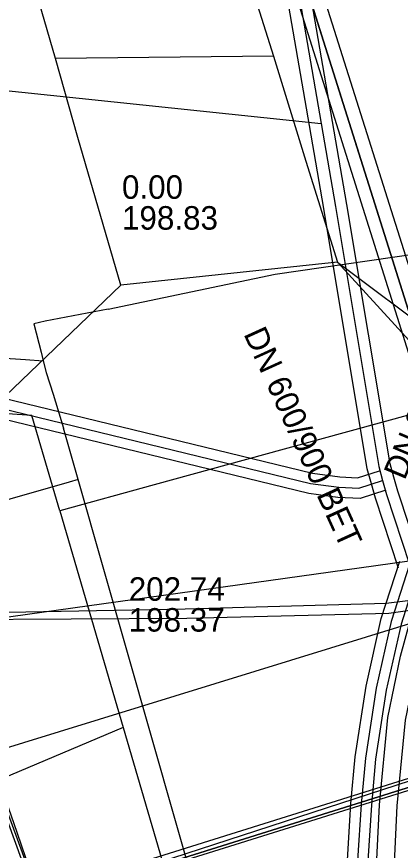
# Model space of a CAD drawing. Extents: x -600309 to -598967, y -1161267 to -1160292.
# Drawn here: x -599245.49 to -599232.41, y -1161251.1 to -1161222.72 of the extents above; entities that cross this region are included whole.
import ezdxf

# ---------------------------------------------------------------- set-up
doc = ezdxf.new("R2010")
doc.units = 0
for name, color, linetype in [('Vrstva 10', 7, 'Continuous'), ('Vrstva 12', 7, 'Continuous'), ('Vrstva 13', 7, 'Continuous'), ('Vrstva 16', 7, 'Continuous'), ('Vrstva 42', 7, 'Continuous'), ('Vrstva 44', 7, 'Continuous'), ('Vrstva 54', 7, 'Continuous'), ('Vrstva 55', 7, 'Continuous'), ('Vrstva 58', 7, 'Continuous'), ('Vrstva 9', 7, 'Continuous')]:
    doc.layers.add(name, color=color, linetype=linetype)

msp = doc.modelspace()

# ---------------------------------------------------------------- linework, layer by layer
at = {"layer": 'Vrstva 10'}
for p, q in [((-599237.17, -1161218.22), (-599221.784, -1161267.031)), ((-599236.22, -1161218.29), (-599220.801, -1161267.031)), ((-599234.235, -1161229.117), (-599234.724, -1161226.291)), ((-599235.024, -1161229.254), (-599235.513, -1161226.427))]:
    msp.add_line(p, q, dxfattribs=at)
for points in [[(-599234.724, -1161226.291), (-599239.864, -1161196.586), (-599240.106, -1161195.933), (-599240.701, -1161195.25)], [(-599235.513, -1161226.427), (-599240.639, -1161196.796), (-599240.805, -1161196.348), (-599241.304, -1161195.776)], [(-599303.586, -1161224.015), (-599302.565, -1161223.81), (-599300.956, -1161223.673), (-599298.819, -1161223.863), (-599269.258, -1161230.047), (-599235.407, -1161238.263), (-599234.478, -1161238.388), (-599233.878, -1161238.413), (-599233.122, -1161238.174)], [(-599232.911, -1161238.841), (-599233.784, -1161239.118), (-599234.54, -1161239.086), (-599235.536, -1161238.952), (-599269.412, -1161230.73), (-599298.922, -1161224.556), (-599300.958, -1161224.376), (-599302.466, -1161224.504), (-599303.448, -1161224.701)], [(-599232.632, -1161238.399), (-599232.761, -1161237.939), (-599234.235, -1161229.119)], [(-599233.402, -1161238.616), (-599233.543, -1161238.114), (-599235.024, -1161229.251)], [(-599232.128, -1161264.899), (-599233.007, -1161257.131), (-599233.302, -1161253.253), (-599233.13, -1161249.544), (-599232.846, -1161246.578), (-599232.412, -1161244.49), (-599231.893, -1161242.628), (-599231.118, -1161240.428), (-599230.59, -1161239.025), (-599230.384, -1161238.549)], [(-599231.721, -1161241.239), (-599232.498, -1161238.872), (-599232.632, -1161238.399)], [(-599232.481, -1161241.489), (-599233.263, -1161239.105), (-599233.402, -1161238.616)], [(-599233.254, -1161267.031), (-599233.556, -1161264.434), (-599234.128, -1161257.18), (-599234.257, -1161253.455), (-599234.219, -1161251.431), (-599234.1, -1161249.506), (-599233.952, -1161247.913), (-599233.584, -1161245.509), (-599233.064, -1161243.21), (-599232.434, -1161241.256)], [(-599231.768, -1161241.471), (-599232.388, -1161243.395), (-599232.896, -1161245.639), (-599233.257, -1161247.998), (-599233.402, -1161249.56), (-599233.52, -1161251.459), (-599233.557, -1161253.449), (-599233.428, -1161257.141), (-599232.859, -1161264.366), (-599232.549, -1161267.031)]]:
    msp.add_lwpolyline(points, dxfattribs=at)
at = {"layer": 'Vrstva 12'}
msp.add_lwpolyline([(-599236.566, -1161216.582), (-599236.7, -1161218.26), (-599221.296, -1161267.031)], dxfattribs=at)
at = {"layer": 'Vrstva 13'}
for p, q in [((-599242.367, -1161232.679), (-599236.681, -1161231.481)), ((-599242.368, -1161232.68), (-599244.52, -1161233.089)), ((-599244.651, -1161234.136), (-599244.583, -1161234.434)), ((-599245.192, -1161234.386), (-599244.583, -1161234.434)), ((-599244.583, -1161234.434), (-599244.48, -1161234.83))]:
    msp.add_line(p, q, dxfattribs=at)
for points in [[(-599236.681, -1161231.481), (-599227.041, -1161230.092), (-599220.213, -1161229.089), (-599218.605, -1161228.856), (-599213.52, -1161225.93), (-599212.696, -1161225.456), (-599207.28, -1161222.57), (-599199.078, -1161218.2), (-599178.982, -1161207.493), (-599178.382, -1161207.174), (-599172.904, -1161200.579), (-599163.903, -1161197.661), (-599156.96, -1161195.41), (-599145.531, -1161191.704), (-599133.008, -1161187.644), (-599113.264, -1161181.224), (-599091.42, -1161174.16), (-599091.258, -1161174.108)], [(-599244.52, -1161233.089), (-599244.904, -1161233.177), (-599244.651, -1161234.136)], [(-599309.236, -1161236.401), (-599308.711, -1161236.195), (-599301.83, -1161233.38), (-599280.01, -1161233.75), (-599252.11, -1161233.94), (-599245.192, -1161234.386)], [(-599244.48, -1161234.83), (-599244.25, -1161235.574), (-599243.898, -1161236.727)], [(-599235.239, -1161267.031), (-599239.225, -1161253.08), (-599243.397, -1161238.479), (-599243.898, -1161236.727)], [(-599243.397, -1161238.479), (-599243.705, -1161238.567), (-599258.103, -1161242.681)]]:
    msp.add_lwpolyline(points, dxfattribs=at)
at = {"layer": 'Vrstva 16'}
for points in [[(-599233.23, -1161187.33), (-599232.94, -1161188.29), (-599231.48, -1161193.07), (-599230.03, -1161197.85), (-599219.69, -1161231.83), (-599224.76, -1161234.26), (-599231.93, -1161236.23), (-599236.37, -1161237.44), (-599240.8, -1161238.66), (-599244.02, -1161239.54)], [(-599244.02, -1161239.54), (-599244.97, -1161236.3), (-599246.47, -1161236.19)], [(-599244.02, -1161239.54), (-599241.86, -1161246.92), (-599237.82, -1161260.72), (-599235.976, -1161267.031)], [(-599241.86, -1161246.92), (-599250.65, -1161250.63)]]:
    msp.add_lwpolyline(points, dxfattribs=at)
at = {"layer": 'Vrstva 42'}
for points in [[(-599287.233, -1161229.97), (-599281.039, -1161229.59), (-599271.815, -1161230.301), (-599265.927, -1161231.054), (-599259.601, -1161231.863), (-599255.835, -1161232.878), (-599254.093, -1161234.988), (-599251.102, -1161241.051), (-599248.858, -1161247.351), (-599246.943, -1161252.939), (-599246.841, -1161253.236), (-599246.707, -1161253.195), (-599244.843, -1161252.625), (-599230.966, -1161248.274), (-599224.086, -1161245.855), (-599223.848, -1161245.926), (-599223.518, -1161246.105), (-599222.38, -1161246.804), (-599219.827, -1161252.523), (-599219.826, -1161252.528), (-599215.625, -1161264.197), (-599214.673, -1161267.031)], [(-599287.233, -1161229.97), (-599281.039, -1161229.59), (-599271.815, -1161230.301), (-599265.927, -1161231.054), (-599259.601, -1161231.863), (-599255.835, -1161232.878), (-599254.093, -1161234.988), (-599251.102, -1161241.051), (-599248.858, -1161247.351), (-599246.943, -1161252.939), (-599246.841, -1161253.236), (-599246.707, -1161253.195), (-599244.843, -1161252.625), (-599230.966, -1161248.274), (-599224.086, -1161245.855), (-599223.848, -1161245.926), (-599223.518, -1161246.105), (-599222.38, -1161246.804), (-599219.827, -1161252.523), (-599219.826, -1161252.528), (-599215.625, -1161264.197), (-599214.673, -1161267.031)], [(-599287.233, -1161229.97), (-599281.039, -1161229.59), (-599271.815, -1161230.301), (-599265.927, -1161231.054), (-599259.601, -1161231.863), (-599255.835, -1161232.878), (-599254.093, -1161234.988), (-599251.102, -1161241.051), (-599248.858, -1161247.351), (-599246.943, -1161252.939), (-599246.841, -1161253.236), (-599246.707, -1161253.195), (-599244.843, -1161252.625), (-599230.966, -1161248.274), (-599224.086, -1161245.855), (-599223.848, -1161245.926), (-599223.518, -1161246.105), (-599222.38, -1161246.804), (-599219.827, -1161252.523), (-599219.826, -1161252.528), (-599215.625, -1161264.197), (-599214.673, -1161267.031)], [(-599287.233, -1161229.97), (-599281.039, -1161229.59), (-599271.815, -1161230.301), (-599265.927, -1161231.054), (-599259.601, -1161231.863), (-599255.835, -1161232.878), (-599254.093, -1161234.988), (-599251.102, -1161241.051), (-599248.858, -1161247.351), (-599246.943, -1161252.939), (-599246.841, -1161253.236), (-599246.707, -1161253.195), (-599244.843, -1161252.625), (-599230.966, -1161248.274), (-599224.086, -1161245.855), (-599223.848, -1161245.926), (-599223.518, -1161246.105), (-599222.38, -1161246.804), (-599219.827, -1161252.523), (-599219.826, -1161252.528), (-599215.625, -1161264.197), (-599214.673, -1161267.031)], [(-599287.233, -1161229.97), (-599281.039, -1161229.59), (-599271.815, -1161230.301), (-599265.927, -1161231.054), (-599259.601, -1161231.863), (-599255.835, -1161232.878), (-599254.093, -1161234.988), (-599251.102, -1161241.051), (-599248.858, -1161247.351), (-599246.943, -1161252.939), (-599246.841, -1161253.236), (-599246.707, -1161253.195), (-599244.843, -1161252.625), (-599230.966, -1161248.274), (-599224.086, -1161245.855), (-599223.848, -1161245.926), (-599223.518, -1161246.105), (-599222.38, -1161246.804), (-599219.827, -1161252.523), (-599219.826, -1161252.528), (-599215.625, -1161264.197), (-599214.673, -1161267.031)], [(-599287.233, -1161229.97), (-599281.039, -1161229.59), (-599271.815, -1161230.301), (-599265.927, -1161231.054), (-599259.601, -1161231.863), (-599255.835, -1161232.878), (-599254.093, -1161234.988), (-599251.102, -1161241.051), (-599248.858, -1161247.351), (-599246.943, -1161252.939), (-599246.841, -1161253.236), (-599246.707, -1161253.195), (-599244.843, -1161252.625), (-599230.966, -1161248.274), (-599224.086, -1161245.855), (-599223.848, -1161245.926), (-599223.518, -1161246.105), (-599222.38, -1161246.804), (-599219.827, -1161252.523), (-599219.826, -1161252.528), (-599215.625, -1161264.197), (-599214.673, -1161267.031)], [(-599214.99, -1161267.031), (-599215.909, -1161264.295), (-599220.118, -1161252.604), (-599220.117, -1161252.609), (-599222.616, -1161247.011), (-599223.668, -1161246.365), (-599223.964, -1161246.204), (-599224.078, -1161246.171), (-599230.872, -1161248.558), (-599244.755, -1161252.911), (-599247.032, -1161253.607), (-599247.069, -1161253.498), (-599247.226, -1161253.04), (-599249.142, -1161247.449), (-599251.378, -1161241.169), (-599254.347, -1161235.152), (-599256.005, -1161233.142), (-599259.659, -1161232.157), (-599265.967, -1161231.35), (-599271.845, -1161230.599), (-599281.041, -1161229.89), (-599287.207, -1161230.27)], [(-599287.207, -1161230.27), (-599281.041, -1161229.89), (-599271.845, -1161230.599), (-599265.967, -1161231.35), (-599259.659, -1161232.157), (-599256.005, -1161233.142), (-599254.347, -1161235.152), (-599251.378, -1161241.169), (-599249.142, -1161247.449), (-599247.226, -1161253.04), (-599247.069, -1161253.498), (-599247.032, -1161253.607), (-599244.755, -1161252.911), (-599230.872, -1161248.558), (-599224.078, -1161246.171), (-599223.964, -1161246.204), (-599223.668, -1161246.365), (-599222.616, -1161247.011), (-599220.117, -1161252.609), (-599220.118, -1161252.604), (-599215.909, -1161264.295), (-599214.99, -1161267.031)], [(-599287.207, -1161230.27), (-599281.041, -1161229.89), (-599271.845, -1161230.599), (-599265.967, -1161231.35), (-599259.659, -1161232.157), (-599256.005, -1161233.142), (-599254.347, -1161235.152), (-599251.378, -1161241.169), (-599249.142, -1161247.449), (-599247.226, -1161253.04), (-599247.069, -1161253.498), (-599247.032, -1161253.607), (-599244.755, -1161252.911), (-599230.872, -1161248.558), (-599224.078, -1161246.171), (-599223.964, -1161246.204), (-599223.668, -1161246.365), (-599222.616, -1161247.011), (-599220.117, -1161252.609), (-599220.118, -1161252.604), (-599215.909, -1161264.295), (-599214.99, -1161267.031)], [(-599287.207, -1161230.27), (-599281.041, -1161229.89), (-599271.845, -1161230.599), (-599265.967, -1161231.35), (-599259.659, -1161232.157), (-599256.005, -1161233.142), (-599254.347, -1161235.152), (-599251.378, -1161241.169), (-599249.142, -1161247.449), (-599247.226, -1161253.04), (-599247.069, -1161253.498), (-599247.032, -1161253.607), (-599244.755, -1161252.911), (-599230.872, -1161248.558), (-599224.078, -1161246.171), (-599223.964, -1161246.204), (-599223.668, -1161246.365), (-599222.616, -1161247.011), (-599220.117, -1161252.609), (-599220.118, -1161252.604), (-599215.909, -1161264.295), (-599214.99, -1161267.031)], [(-599220.655, -1161251.685), (-599222.697, -1161247.066), (-599224.008, -1161246.259), (-599230.862, -1161248.665), (-599247.073, -1161253.718), (-599249.188, -1161247.48), (-599251.449, -1161241.182), (-599254.399, -1161235.148), (-599256.016, -1161233.168), (-599259.682, -1161232.206), (-599271.855, -1161230.672), (-599281.033, -1161229.951), (-599287.119, -1161230.329)], [(-599271.845, -1161230.599), (-599265.967, -1161231.35), (-599259.659, -1161232.157), (-599256.005, -1161233.142), (-599254.347, -1161235.152), (-599251.378, -1161241.169), (-599249.142, -1161247.449), (-599247.226, -1161253.04), (-599247.069, -1161253.498), (-599247.032, -1161253.607), (-599244.755, -1161252.911), (-599230.872, -1161248.558), (-599224.078, -1161246.171), (-599223.964, -1161246.204), (-599223.668, -1161246.365), (-599222.616, -1161247.011), (-599220.117, -1161252.609), (-599220.118, -1161252.604), (-599215.909, -1161264.295), (-599214.99, -1161267.031)], [(-599265.967, -1161231.35), (-599259.659, -1161232.157), (-599256.005, -1161233.142), (-599254.347, -1161235.152), (-599251.378, -1161241.169), (-599249.142, -1161247.449), (-599247.226, -1161253.04), (-599247.069, -1161253.498), (-599247.032, -1161253.607), (-599244.755, -1161252.911), (-599230.872, -1161248.558), (-599224.078, -1161246.171), (-599223.964, -1161246.204), (-599223.668, -1161246.365), (-599222.616, -1161247.011), (-599220.117, -1161252.609), (-599220.118, -1161252.604), (-599215.909, -1161264.295), (-599214.99, -1161267.031)]]:
    msp.add_lwpolyline(points, dxfattribs=at)
at = {"layer": 'Vrstva 44'}
for points in [[(-599205.02, -1161224.23), (-599208.9, -1161226.71), (-599213.59, -1161229.54), (-599216.66, -1161231.58), (-599219.28, -1161233.32), (-599221.17, -1161235.18), (-599223.81, -1161239.21), (-599224.3, -1161240.91), (-599224.41, -1161241.44), (-599224.61, -1161241.62), (-599224.83, -1161241.71), (-599232.9, -1161242.7), (-599239.75, -1161242.89), (-599247.61, -1161243.04), (-599248.77, -1161242.91), (-599249.91, -1161242.51), (-599250.96, -1161241.75), (-599251.85, -1161240.71), (-599253.77, -1161238.01), (-599255.96, -1161234.82), (-599256.47, -1161234.35), (-599258.652, -1161232.996)], [(-599204.9, -1161224.46), (-599208.71, -1161227.01), (-599213.43, -1161229.75), (-599216.42, -1161231.83), (-599219.19, -1161233.43), (-599221.08, -1161235.48), (-599223.59, -1161239.31), (-599224.07, -1161240.94), (-599224.16, -1161241.56), (-599224.5, -1161241.8), (-599224.82, -1161241.89), (-599232.81, -1161243.03), (-599239.69, -1161243.2), (-599247.58, -1161243.25), (-599248.74, -1161243.21), (-599250.02, -1161242.75), (-599251.17, -1161242.03), (-599252.15, -1161240.92), (-599254.02, -1161238.16), (-599256.1, -1161234.96), (-599256.55, -1161234.54), (-599258.786, -1161233.206)]]:
    msp.add_lwpolyline(points, dxfattribs=at)
at = {"layer": 'Vrstva 54'}
for points in [[(-599237.89, -1161220.39), (-599236.74, -1161224.07)], [(-599244.17, -1161224.15), (-599245.1, -1161220.93)], [(-599236.74, -1161224.07), (-599244.17, -1161224.15)], [(-599236.74, -1161224.07), (-599235.63, -1161227.64)], [(-599243.4, -1161226.83), (-599244.17, -1161224.15)], [(-599241.94, -1161231.86), (-599243.4, -1161226.83)], [(-599235.63, -1161227.64), (-599234.56, -1161231.08)], [(-599234.56, -1161231.08), (-599241.94, -1161231.86)], [(-599226.01, -1161240.4), (-599234.56, -1161231.08)], [(-599234.56, -1161231.08), (-599224.37, -1161238.7)], [(-599241.94, -1161231.86), (-599254.33, -1161243.73)], [(-599226.01, -1161240.4), (-599253.91, -1161244.297)]]:
    msp.add_lwpolyline(points, dxfattribs=at)
at = {"layer": 'Vrstva 55'}
for points in [[(-599240.463, -1161267.031), (-599241.26, -1161264.43), (-599241.94, -1161262.26), (-599242.11, -1161260.27), (-599246.2, -1161249.01), (-599246.62, -1161247.85), (-599224.32, -1161240.98), (-599223.09, -1161240.6), (-599220.14, -1161236.56), (-599219.73, -1161236.06), (-599216.11, -1161232.41), (-599213.28, -1161230.52), (-599204.97, -1161225.61), (-599197.73, -1161221.45), (-599197.37, -1161221.85), (-599196.8, -1161221.97)], [(-599240.477, -1161267.031), (-599241.77, -1161262.59), (-599242.1, -1161259.89), (-599246.49, -1161247.92), (-599249.86, -1161241.34), (-599256.27, -1161239.65), (-599256.27, -1161236.11), (-599253.07, -1161234.43), (-599256.1, -1161232.07), (-599261.84, -1161231.05), (-599261.81, -1161230.13)]]:
    msp.add_lwpolyline(points, dxfattribs=at)
at = {"layer": 'Vrstva 58'}
for points in [[(-599221.296, -1161267.031), (-599235.566, -1161221.85), (-599236.7, -1161218.26), (-599236.59, -1161216.58), (-599236.43, -1161214.87), (-599238.8, -1161191.15), (-599239.11, -1161189.29), (-599239.44, -1161187.48), (-599244.31, -1161141.04), (-599244.57, -1161137.51), (-599242.85, -1161137.28), (-599204.2, -1161127.99), (-599200.89, -1161127.16), (-599145.8, -1161118.43), (-599142.33, -1161117.89), (-599142.31, -1161116.76), (-599137.63, -1161099.39), (-599137.45, -1161097.68)], [(-599221.296, -1161267.031), (-599235.566, -1161221.85), (-599236.7, -1161218.26), (-599236.59, -1161216.58), (-599236.43, -1161214.87), (-599238.8, -1161191.15), (-599239.11, -1161189.29), (-599239.44, -1161187.48), (-599244.31, -1161141.04), (-599244.57, -1161137.51), (-599242.85, -1161137.28), (-599204.2, -1161127.99), (-599200.89, -1161127.16), (-599145.8, -1161118.43), (-599142.33, -1161117.89), (-599142.31, -1161116.76), (-599137.63, -1161099.39), (-599137.45, -1161097.68)], [(-599221.296, -1161267.031), (-599235.566, -1161221.85), (-599236.7, -1161218.26), (-599236.59, -1161216.58), (-599236.43, -1161214.87), (-599238.8, -1161191.15), (-599239.11, -1161189.29), (-599239.44, -1161187.48), (-599244.31, -1161141.04), (-599244.57, -1161137.51), (-599242.85, -1161137.28), (-599204.2, -1161127.99), (-599200.89, -1161127.16), (-599145.8, -1161118.43), (-599142.33, -1161117.89), (-599142.31, -1161116.76), (-599137.63, -1161099.39), (-599137.45, -1161097.68)], [(-599214.748, -1161267.031), (-599215.542, -1161264.678), (-599221.793, -1161247.066), (-599223.951, -1161246.082), (-599246.895, -1161253.54), (-599250.766, -1161242.274), (-599251.115, -1161241.069), (-599253.971, -1161235.483), (-599256.002, -1161233.04), (-599268.061, -1161230.946), (-599281.357, -1161229.835), (-599292.528, -1161230.596)], [(-599246.46, -1161247.59), (-599246.165, -1161248.552), (-599245.48, -1161250.48), (-599243.85, -1161255.26), (-599242.93, -1161257.6), (-599242.73, -1161257.98), (-599241.746, -1161260.923)]]:
    msp.add_lwpolyline(points, dxfattribs=at)
at = {"layer": 'Vrstva 9'}
msp.add_line((-599235.118, -1161226.359), (-599234.629, -1161229.185), dxfattribs=at)
for points in [[(-599241.003, -1161195.513), (-599240.456, -1161196.141), (-599240.252, -1161196.691), (-599235.118, -1161226.359)], [(-599267.209, -1161223.005), (-599254.552, -1161224.328), (-599235.118, -1161226.359)], [(-599303.517, -1161224.358), (-599302.515, -1161224.157), (-599300.957, -1161224.025), (-599298.871, -1161224.21), (-599269.335, -1161230.389), (-599235.472, -1161238.607), (-599234.509, -1161238.737), (-599233.831, -1161238.766), (-599233.017, -1161238.507)], [(-599234.629, -1161229.185), (-599233.152, -1161238.026), (-599233.017, -1161238.507)], [(-599233.017, -1161238.507), (-599232.881, -1161238.989), (-599232.101, -1161241.364)], [(-599229.834, -1161238.788), (-599230.034, -1161239.25), (-599230.554, -1161240.634), (-599231.32, -1161242.809), (-599231.829, -1161244.632), (-599232.252, -1161246.668), (-599232.531, -1161249.586), (-599232.701, -1161253.244), (-599232.409, -1161257.074), (-599231.532, -1161264.831)], [(-599232.101, -1161241.364), (-599232.726, -1161243.302), (-599233.24, -1161245.574), (-599233.604, -1161247.956), (-599233.751, -1161249.533), (-599233.869, -1161251.445), (-599233.907, -1161253.452), (-599233.778, -1161257.161), (-599233.207, -1161264.4), (-599232.902, -1161267.031)]]:
    msp.add_lwpolyline(points, dxfattribs=at)

# ---------------------------------------------------------------- texts
at = {"layer": 'Vrstva 12'}
for s, p in [('0.00', (-599241.901, -1161228.92)), ('198.83', (-599241.901, -1161229.97)), ('202.74', (-599241.67, -1161242.602)), ('198.37', (-599241.67, -1161243.652))]:
    msp.add_text(s, height=0.8, dxfattribs=at).set_placement(p)
for s, rotation, p in [('DN 800/1200 BET', 67.1197, (-599232.27, -1161238.525)), ('DN 600/900 BET', 294.4386, (-599237.768, -1161233.516))]:
    msp.add_text(s, height=0.8, rotation=rotation, dxfattribs=at).set_placement(p)

doc.saveas('drawing.dxf')
